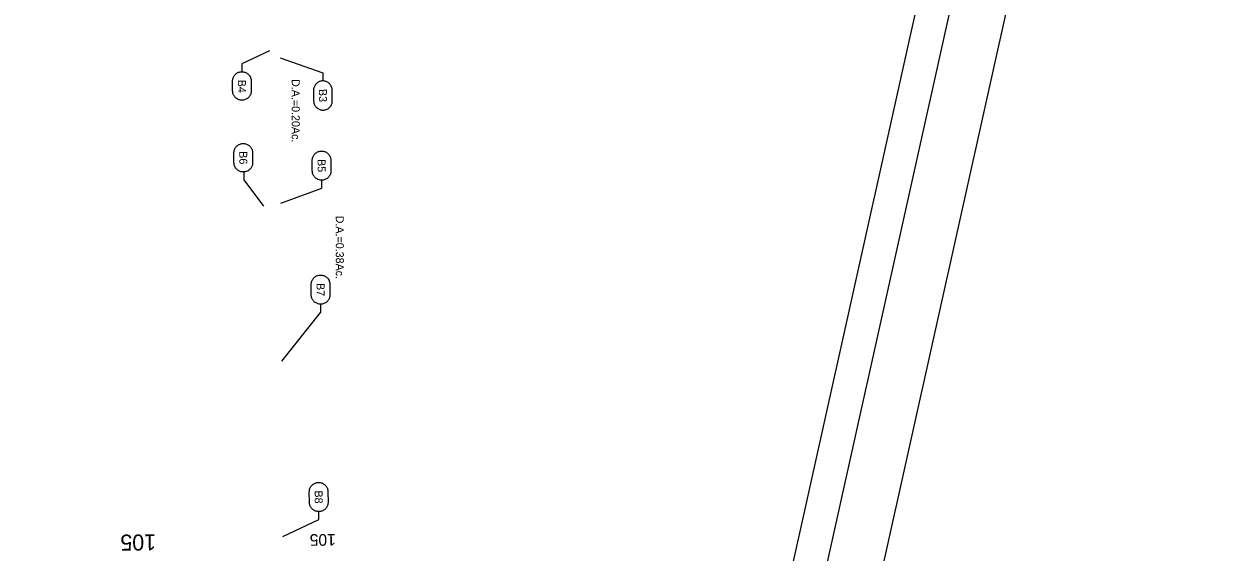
# Model space of a CAD drawing. Extents: x 2149887 to 2151449, y 143603 to 146901.
# Drawn here: x 2150552 to 2151449, y 145510 to 145906 of the extents above; entities that cross this region are included whole.
import ezdxf

# ---------------------------------------------------------------- set-up
doc = ezdxf.new("R2010")
doc.units = 0
for name, color, linetype in [('EX_Align_Sta', 7, 'Continuous'), ('PR_Storm_Drainage_Area_Txt', 7, 'Continuous'), ('PR_Storm_Txt', 7, 'Continuous'), ('SHT_Plot_Shape_Full', 7, 'Continuous'), ('SHT_Plot_Shape_Half', 7, 'Continuous'), ('SHT_Sheet_Border', 7, 'Continuous'), ('TOPO_DRAIN_Manhole', 7, 'Continuous')]:
    doc.layers.add(name, color=color, linetype=linetype)

msp = doc.modelspace()

# ---------------------------------------------------------------- linework, layer by layer
at = {"layer": 'PR_Storm_Txt'}
for points in [[(2150735.82, 145885.73), (2150715.07, 145876.07), (2150715.1, 145870.07)], [(2150743.77, 145880.4), (2150775.71, 145869.14), (2150775.77, 145863.14)], [(2150731.46, 145769.14), (2150716.9, 145788.9), (2150716.86, 145794.9)], [(2150744.42, 145771.47), (2150774.99, 145782.72), (2150774.96, 145788.72)], [(2150745.14, 145652.91), (2150774.24, 145689.76), (2150774.2, 145695.76)], [(2150745.93, 145521.47), (2150772.81, 145534.21), (2150772.77, 145540.2)]]:
    msp.add_lwpolyline(points, dxfattribs=at)
for points in [[(2150708.19, 145855.66), (2150708.15, 145863.03), (2150708.17, 145863.64), (2150708.25, 145864.25), (2150708.37, 145864.84), (2150708.55, 145865.43), (2150708.78, 145865.99), (2150709.06, 145866.54), (2150709.39, 145867.05), (2150709.76, 145867.54), (2150710.17, 145867.99), (2150710.61, 145868.41), (2150711.1, 145868.78), (2150711.61, 145869.11), (2150712.15, 145869.4), (2150712.71, 145869.64), (2150713.29, 145869.82), (2150713.89, 145869.96), (2150714.49, 145870.04), (2150715.1, 145870.07), (2150715.1, 145870.07), (2150715.71, 145870.05), (2150716.32, 145869.97), (2150716.92, 145869.84), (2150717.5, 145869.66), (2150718.07, 145869.43), (2150718.61, 145869.16), (2150719.13, 145868.83), (2150719.61, 145868.46), (2150720.07, 145868.05), (2150720.48, 145867.6), (2150720.86, 145867.12), (2150721.19, 145866.61), (2150721.47, 145866.07), (2150721.71, 145865.51), (2150721.9, 145864.93), (2150722.03, 145864.33), (2150722.12, 145863.72), (2150722.15, 145863.11), (2150722.19, 145855.75), (2150722.17, 145855.14), (2150722.09, 145854.53), (2150721.96, 145853.93), (2150721.78, 145853.35), (2150721.55, 145852.78), (2150721.27, 145852.24), (2150720.95, 145851.72), (2150720.58, 145851.24), (2150720.17, 145850.78), (2150719.72, 145850.37), (2150719.24, 145849.99), (2150718.73, 145849.66), (2150718.19, 145849.38), (2150717.62, 145849.14), (2150717.04, 145848.95), (2150716.45, 145848.82), (2150715.84, 145848.73), (2150715.23, 145848.7), (2150715.23, 145848.7), (2150714.62, 145848.73), (2150714.02, 145848.8), (2150713.42, 145848.93), (2150712.84, 145849.11), (2150712.27, 145849.34), (2150711.73, 145849.62), (2150711.21, 145849.95), (2150710.72, 145850.32), (2150710.27, 145850.73), (2150709.86, 145851.17), (2150709.48, 145851.66), (2150709.15, 145852.17), (2150708.86, 145852.71), (2150708.63, 145853.27), (2150708.44, 145853.85), (2150708.3, 145854.45), (2150708.22, 145855.05)], [(2150768.84, 145856.07), (2150768.92, 145848.23), (2150768.96, 145847.62), (2150769.04, 145847.01), (2150769.18, 145846.42), (2150769.37, 145845.84), (2150769.61, 145845.28), (2150769.9, 145844.74), (2150770.23, 145844.23), (2150770.61, 145843.75), (2150771.03, 145843.3), (2150771.48, 145842.89), (2150771.97, 145842.52), (2150772.49, 145842.2), (2150773.03, 145841.93), (2150773.6, 145841.7), (2150774.18, 145841.52), (2150774.78, 145841.39), (2150775.39, 145841.32), (2150776, 145841.3), (2150776, 145841.3), (2150776.61, 145841.33), (2150777.21, 145841.42), (2150777.81, 145841.56), (2150778.39, 145841.75), (2150778.95, 145841.99), (2150779.49, 145842.27), (2150780, 145842.61), (2150780.48, 145842.98), (2150780.92, 145843.4), (2150781.33, 145843.86), (2150781.7, 145844.34), (2150782.02, 145844.86), (2150782.3, 145845.41), (2150782.53, 145845.97), (2150782.7, 145846.56), (2150782.83, 145847.16), (2150782.9, 145847.76), (2150782.92, 145848.37), (2150782.84, 145856.21), (2150782.81, 145856.82), (2150782.72, 145857.43), (2150782.59, 145858.02), (2150782.4, 145858.6), (2150782.16, 145859.17), (2150781.87, 145859.7), (2150781.53, 145860.22), (2150781.16, 145860.7), (2150780.74, 145861.14), (2150780.29, 145861.55), (2150779.8, 145861.92), (2150779.28, 145862.24), (2150778.74, 145862.52), (2150778.17, 145862.74), (2150777.58, 145862.92), (2150776.99, 145863.05), (2150776.38, 145863.12), (2150775.77, 145863.14), (2150775.77, 145863.14), (2150775.16, 145863.11), (2150774.56, 145863.02), (2150773.96, 145862.88), (2150773.38, 145862.69), (2150772.82, 145862.46), (2150772.28, 145862.17), (2150771.77, 145861.83), (2150771.29, 145861.46), (2150770.84, 145861.04), (2150770.43, 145860.59), (2150770.07, 145860.1), (2150769.74, 145859.58), (2150769.47, 145859.03), (2150769.24, 145858.47), (2150769.06, 145857.88), (2150768.94, 145857.29), (2150768.86, 145856.68)], [(2150709.21, 145801.82), (2150709.17, 145809.19), (2150709.19, 145809.8), (2150709.26, 145810.41), (2150709.39, 145811.01), (2150709.57, 145811.59), (2150709.8, 145812.16), (2150710.08, 145812.7), (2150710.41, 145813.22), (2150710.78, 145813.7), (2150711.19, 145814.15), (2150711.63, 145814.57), (2150712.12, 145814.94), (2150712.63, 145815.28), (2150713.17, 145815.56), (2150713.73, 145815.8), (2150714.31, 145815.99), (2150714.91, 145816.12), (2150715.51, 145816.2), (2150716.12, 145816.23), (2150716.12, 145816.23), (2150716.73, 145816.21), (2150717.34, 145816.14), (2150717.94, 145816.01), (2150718.52, 145815.83), (2150719.09, 145815.6), (2150719.63, 145815.32), (2150720.15, 145814.99), (2150720.63, 145814.62), (2150721.09, 145814.21), (2150721.5, 145813.77), (2150721.88, 145813.28), (2150722.21, 145812.77), (2150722.49, 145812.23), (2150722.73, 145811.67), (2150722.92, 145811.09), (2150723.05, 145810.49), (2150723.13, 145809.89), (2150723.17, 145809.28), (2150723.21, 145801.91), (2150723.19, 145801.3), (2150723.11, 145800.69), (2150722.98, 145800.1), (2150722.8, 145799.51), (2150722.57, 145798.95), (2150722.29, 145798.4), (2150721.97, 145797.89), (2150721.6, 145797.4), (2150721.19, 145796.95), (2150720.74, 145796.53), (2150720.26, 145796.16), (2150719.75, 145795.83), (2150719.21, 145795.54), (2150718.64, 145795.3), (2150718.06, 145795.12), (2150717.47, 145794.98), (2150716.86, 145794.9), (2150716.25, 145794.87), (2150716.25, 145794.87), (2150715.64, 145794.89), (2150715.04, 145794.97), (2150714.44, 145795.09), (2150713.86, 145795.27), (2150713.29, 145795.5), (2150712.75, 145795.78), (2150712.23, 145796.11), (2150711.74, 145796.48), (2150711.29, 145796.89), (2150710.87, 145797.34), (2150710.5, 145797.82), (2150710.17, 145798.33), (2150709.88, 145798.87), (2150709.65, 145799.43), (2150709.46, 145800.01), (2150709.32, 145800.61), (2150709.24, 145801.21)], [(2150767.92, 145795.68), (2150767.87, 145803.52), (2150767.89, 145804.13), (2150767.97, 145804.74), (2150768.1, 145805.33), (2150768.28, 145805.92), (2150768.51, 145806.48), (2150768.79, 145807.03), (2150769.11, 145807.54), (2150769.48, 145808.03), (2150769.89, 145808.48), (2150770.34, 145808.9), (2150770.82, 145809.27), (2150771.33, 145809.6), (2150771.87, 145809.89), (2150772.44, 145810.13), (2150773.02, 145810.31), (2150773.61, 145810.45), (2150774.22, 145810.53), (2150774.83, 145810.56), (2150774.83, 145810.56), (2150775.44, 145810.54), (2150776.04, 145810.46), (2150776.64, 145810.34), (2150777.22, 145810.16), (2150777.79, 145809.93), (2150778.33, 145809.65), (2150778.85, 145809.32), (2150779.34, 145808.95), (2150779.79, 145808.54), (2150780.2, 145808.1), (2150780.58, 145807.61), (2150780.91, 145807.1), (2150781.19, 145806.56), (2150781.43, 145806), (2150781.62, 145805.42), (2150781.75, 145804.82), (2150781.84, 145804.22), (2150781.87, 145803.61), (2150781.92, 145795.76), (2150781.89, 145795.15), (2150781.82, 145794.55), (2150781.69, 145793.95), (2150781.51, 145793.37), (2150781.28, 145792.8), (2150781, 145792.26), (2150780.67, 145791.74), (2150780.31, 145791.25), (2150779.9, 145790.8), (2150779.45, 145790.39), (2150778.97, 145790.01), (2150778.45, 145789.68), (2150777.91, 145789.4), (2150777.35, 145789.16), (2150776.77, 145788.97), (2150776.17, 145788.84), (2150775.57, 145788.75), (2150774.96, 145788.72), (2150774.96, 145788.72), (2150774.35, 145788.74), (2150773.74, 145788.82), (2150773.14, 145788.95), (2150772.56, 145789.13), (2150772, 145789.36), (2150771.45, 145789.64), (2150770.94, 145789.96), (2150770.45, 145790.33), (2150770, 145790.74), (2150769.58, 145791.19), (2150769.21, 145791.67), (2150768.87, 145792.19), (2150768.59, 145792.73), (2150768.35, 145793.29), (2150768.17, 145793.87), (2150768.03, 145794.46), (2150767.95, 145795.07)], [(2150767.16, 145702.72), (2150767.11, 145710.56), (2150767.14, 145711.17), (2150767.21, 145711.77), (2150767.34, 145712.37), (2150767.52, 145712.95), (2150767.75, 145713.52), (2150768.03, 145714.06), (2150768.36, 145714.58), (2150768.72, 145715.07), (2150769.13, 145715.52), (2150769.58, 145715.94), (2150770.06, 145716.31), (2150770.58, 145716.64), (2150771.12, 145716.93), (2150771.68, 145717.16), (2150772.26, 145717.35), (2150772.86, 145717.49), (2150773.46, 145717.57), (2150774.07, 145717.6), (2150774.07, 145717.6), (2150774.68, 145717.58), (2150775.29, 145717.5), (2150775.88, 145717.37), (2150776.47, 145717.19), (2150777.03, 145716.96), (2150777.58, 145716.68), (2150778.09, 145716.36), (2150778.58, 145715.99), (2150779.03, 145715.58), (2150779.45, 145715.13), (2150779.82, 145714.65), (2150780.15, 145714.14), (2150780.44, 145713.6), (2150780.68, 145713.03), (2150780.86, 145712.45), (2150781, 145711.86), (2150781.08, 145711.25), (2150781.11, 145710.64), (2150781.16, 145702.8), (2150781.14, 145702.19), (2150781.06, 145701.58), (2150780.93, 145700.99), (2150780.75, 145700.4), (2150780.52, 145699.84), (2150780.24, 145699.29), (2150779.92, 145698.78), (2150779.55, 145698.29), (2150779.14, 145697.84), (2150778.69, 145697.42), (2150778.21, 145697.05), (2150777.7, 145696.72), (2150777.16, 145696.43), (2150776.59, 145696.19), (2150776.01, 145696.01), (2150775.42, 145695.87), (2150774.81, 145695.79), (2150774.2, 145695.76), (2150774.2, 145695.76), (2150773.59, 145695.78), (2150772.99, 145695.86), (2150772.39, 145695.99), (2150771.81, 145696.17), (2150771.24, 145696.4), (2150770.7, 145696.68), (2150770.18, 145697), (2150769.69, 145697.37), (2150769.24, 145697.78), (2150768.83, 145698.23), (2150768.45, 145698.71), (2150768.12, 145699.22), (2150767.83, 145699.76), (2150767.6, 145700.32), (2150767.41, 145700.91), (2150767.27, 145701.5), (2150767.19, 145702.11)], [(2150765.73, 145547.16), (2150765.68, 145555), (2150765.71, 145555.62), (2150765.78, 145556.22), (2150765.91, 145556.82), (2150766.09, 145557.4), (2150766.32, 145557.97), (2150766.6, 145558.51), (2150766.93, 145559.03), (2150767.29, 145559.51), (2150767.7, 145559.97), (2150768.15, 145560.38), (2150768.63, 145560.76), (2150769.15, 145561.09), (2150769.69, 145561.37), (2150770.25, 145561.61), (2150770.83, 145561.8), (2150771.43, 145561.93), (2150772.03, 145562.02), (2150772.64, 145562.05), (2150772.64, 145562.05), (2150773.25, 145562.02), (2150773.86, 145561.95), (2150774.46, 145561.82), (2150775.04, 145561.64), (2150775.6, 145561.41), (2150776.15, 145561.13), (2150776.66, 145560.8), (2150777.15, 145560.44), (2150777.6, 145560.03), (2150778.02, 145559.58), (2150778.39, 145559.1), (2150778.73, 145558.58), (2150779.01, 145558.04), (2150779.25, 145557.48), (2150779.43, 145556.9), (2150779.57, 145556.3), (2150779.65, 145555.7), (2150779.68, 145555.09), (2150779.73, 145547.25), (2150779.71, 145546.64), (2150779.63, 145546.03), (2150779.5, 145545.43), (2150779.32, 145544.85), (2150779.09, 145544.28), (2150778.81, 145543.74), (2150778.49, 145543.22), (2150778.12, 145542.74), (2150777.71, 145542.28), (2150777.26, 145541.87), (2150776.78, 145541.5), (2150776.27, 145541.16), (2150775.73, 145540.88), (2150775.16, 145540.64), (2150774.58, 145540.45), (2150773.99, 145540.32), (2150773.38, 145540.24), (2150772.77, 145540.2), (2150772.77, 145540.2), (2150772.16, 145540.23), (2150771.56, 145540.3), (2150770.96, 145540.43), (2150770.38, 145540.61), (2150769.81, 145540.84), (2150769.27, 145541.12), (2150768.75, 145541.45), (2150768.26, 145541.82), (2150767.81, 145542.23), (2150767.4, 145542.67), (2150767.02, 145543.16), (2150766.69, 145543.67), (2150766.4, 145544.21), (2150766.17, 145544.77), (2150765.98, 145545.35), (2150765.84, 145545.95), (2150765.76, 145546.55)]]:
    msp.add_lwpolyline(points, close=True, dxfattribs=at)
at = {"layer": 'SHT_Plot_Shape_Full'}
msp.add_lwpolyline([(2151449.2, 146640.27), (2151058.5, 144883.19), (2149887.11, 145143.65), (2150277.81, 146900.74)], close=True, dxfattribs=at)
at = {"layer": 'SHT_Plot_Shape_Half'}
msp.add_lwpolyline([(2151391.16, 146569.3), (2151022.16, 144909.83), (2149948.39, 145148.59), (2150317.38, 146808.06)], close=True, dxfattribs=at)
at = {"layer": 'SHT_Sheet_Border'}
msp.add_lwpolyline([(2149978.76, 145170.01), (2150320.63, 146707.46), (2151345.59, 146479.55), (2151003.73, 144942.1)], close=True, dxfattribs=at)

# ---------------------------------------------------------------- texts
at = {"layer": 'EX_Align_Sta'}
msp.add_text('105', height=8.75, rotation=180.34426, dxfattribs=at).set_placement((2150785.49, 145523.4))
at = {"layer": 'PR_Storm_Drainage_Area_Txt'}
for s, p in [('D.A.=0.20Ac.', (2150752.52, 145864.57)), ('D.A.=0.38Ac.', (2150785.55, 145762.11))]:
    msp.add_text(s, height=6, rotation=270, dxfattribs=at).set_placement(p)
at = {"layer": 'PR_Storm_Txt'}
for s, rotation, p in [('B4', 270.34424, (2150712.14, 145864.05)), ('B3', 270.59408, (2150772.83, 145857.11)), ('B6', 270.34424, (2150713.16, 145810.41)), ('B5', 270.34424, (2150771.86, 145804.55)), ('B7', 270.34424, (2150771.11, 145711.58)), ('B8', 270.34424, (2150769.68, 145556.03))]:
    msp.add_text(s, height=6, rotation=rotation, dxfattribs=at).set_placement(p)
at = {"layer": 'TOPO_DRAIN_Manhole'}
msp.add_text('105', height=12, rotation=180.34426, dxfattribs=at).set_placement((2150650.76, 145523.11))

doc.saveas('drawing.dxf')
